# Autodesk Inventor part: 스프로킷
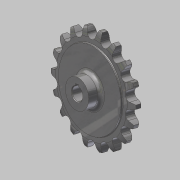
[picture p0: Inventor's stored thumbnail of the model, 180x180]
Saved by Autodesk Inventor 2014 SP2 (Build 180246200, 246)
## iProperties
Created: 2016-03
Part Number: 스프로킷
Material: 강철, 탄소
Document SubType Name: Modeling
Designer: mduedu
Density: 7.87 g/cm^3
Mass: 301.873 g
Surface Area: 120.622 cm^2
Volume: 38.3574 cm^3
Appearance: 반광택
Author: mduedu
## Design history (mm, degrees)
sketch "스케치1"
  geometry: L1 (0, 5)-(29.5, 5); L2 (29.5, 5)-(29.5, 4.1); L3 (30, 3.6)-(33.625, 3.6); L4 (40, 2)-(40, 0); L5 (40, 0)-(0, 0); L6 (0, 0)-(0, 5); L7 (0, -5)-(29.5, -5); L8 (29.5, -5)-(29.5, -4.1); L9 (30, -3.6)-(33.625, -3.6); L10 (40, -2)-(40, 0); L11 (0, 0)-(0, -5); A1 r 13.5 centre (33.625, -9.9) between (40, 2) and (33.625, 3.6); A2 r 13.5 centre (33.625, 9.9) between (33.625, -3.6) and (40, -2); A3 r 0.5 centre (30, 4.1) between (29.5, 4.1) and (30, 3.6); A4 r 0.5 centre (30, -4.1) between (30, -3.6) and (29.5, -4.1); 2 further points
  constraints: 22 end point, 8 point on circle, 6 symmetric about line, 5 tangent, 4 centre point, 4 parallel, 4 point on line, 1 equal radius, 1 horizontal, 1 perpendicular, 1 other
  dimensions: "d0" = 80 diameter of L4 L6; "d2" = 59 diameter of L2 L6; "d3" = 1.6 vertical distance of L4.start L3.end; "d4" = 3.6 distance from line of L4.end L3; "d5" = 5 distance between parallel lines of L5 L1; "d6" = 13.5 radius of A1; "d15" = 0.5 radius of A3
revolve "회전1" sketch "스케치1" stored, may be unused: angle "d7" = 90 deg
sketch "스케치2" dims "d8" = 65.2, "d11" = 80
  geometry: L1 (0, 0)-(0, 32.6); A1 r 36.57 centre (0, 0) between (-16.231, 32.771) and (0, 36.57); A2 r 3.97 centre (0, 36.57) between (-3.866, 35.665) and (0, 32.6); A3 r 12.7 centre (-16.231, 32.771) between (-3.866, 35.665) and (-5.534, 39.615); A4 r 12.7 centre (16.231, 32.771) between (5.534, 39.615) and (3.866, 35.665); A5 r 3.97 centre (0, 36.57) between (0, 32.6) and (3.866, 35.665); A6 r 40 centre (0, 0) between (5.534, 39.615) and (-5.534, 39.615); 2 further points
  constraints: 12 point on circle, 6 centre point, 4 coincident, 3 symmetric about line, 2 end point, 1 point on line, 1 tangent, 1 vertical, 1 vertical alignment, 7 other
  dimensions: "d10" = 73.14 diameter of A1; "d12" = 12.7 radius of A3
extrude "돌출1" cut sketch "스케치2" stored distance "d13" = 10; taper "d14" = 0 deg
sketch "스케치3"
  geometry: C1 r 11 at (0, 0); 1 further point
  constraints: 1 centre point, 1 coincident
  dimensions: "d19" = 22 diameter of C1
extrude "돌출2" join sketch "스케치3" distance "d20" = 10; taper "d21" = 0 deg
fillet "모깎기1" dims "d22" = 3
sketch "스케치4"
  geometry: L1 (-1.5, 0)-(1.5, 0); L2 (1.5, 0)-(1.5, 6.4); L3 (1.5, 6.4)-(-1.5, 6.4); L4 (-1.5, 6.4)-(-1.5, 0); C1 r 5 at (0, 0); 2 further points
  constraints: 8 end point, 2 coincident, 2 parallel, 1 centre point, 1 horizontal, 1 midpoint, 1 perpendicular
  dimensions: "d23" = 10 diameter of C1; "d25" = 3 distance of L2.end L3.end; "d26" = 6.4 distance of L1.end L2.end
extrude "돌출3" cut sketch "스케치4" stored distance "d27" = 8; taper "d28" = 0 deg
chamfer "모따기1" distance "d29" = 0.5; stored, may be unused: second distance "d30" = 2, angle "d31" = 45 deg
sketch "스케치5" dims "d33" = 50
  geometry: C1 r 1 at (0, 25); 2 further points
  constraints: 2 vertical alignment, 1 centre point, 1 coincident, 2 other
  dimensions: "d32" = 2 diameter of C1
extrude "돌출4" join sketch "스케치5" distance "d34" = 0.5; taper "d35" = 0 deg
node "솔리드1"
pattern_circular "원형 패턴1" dims angle "d17" = 360 deg
